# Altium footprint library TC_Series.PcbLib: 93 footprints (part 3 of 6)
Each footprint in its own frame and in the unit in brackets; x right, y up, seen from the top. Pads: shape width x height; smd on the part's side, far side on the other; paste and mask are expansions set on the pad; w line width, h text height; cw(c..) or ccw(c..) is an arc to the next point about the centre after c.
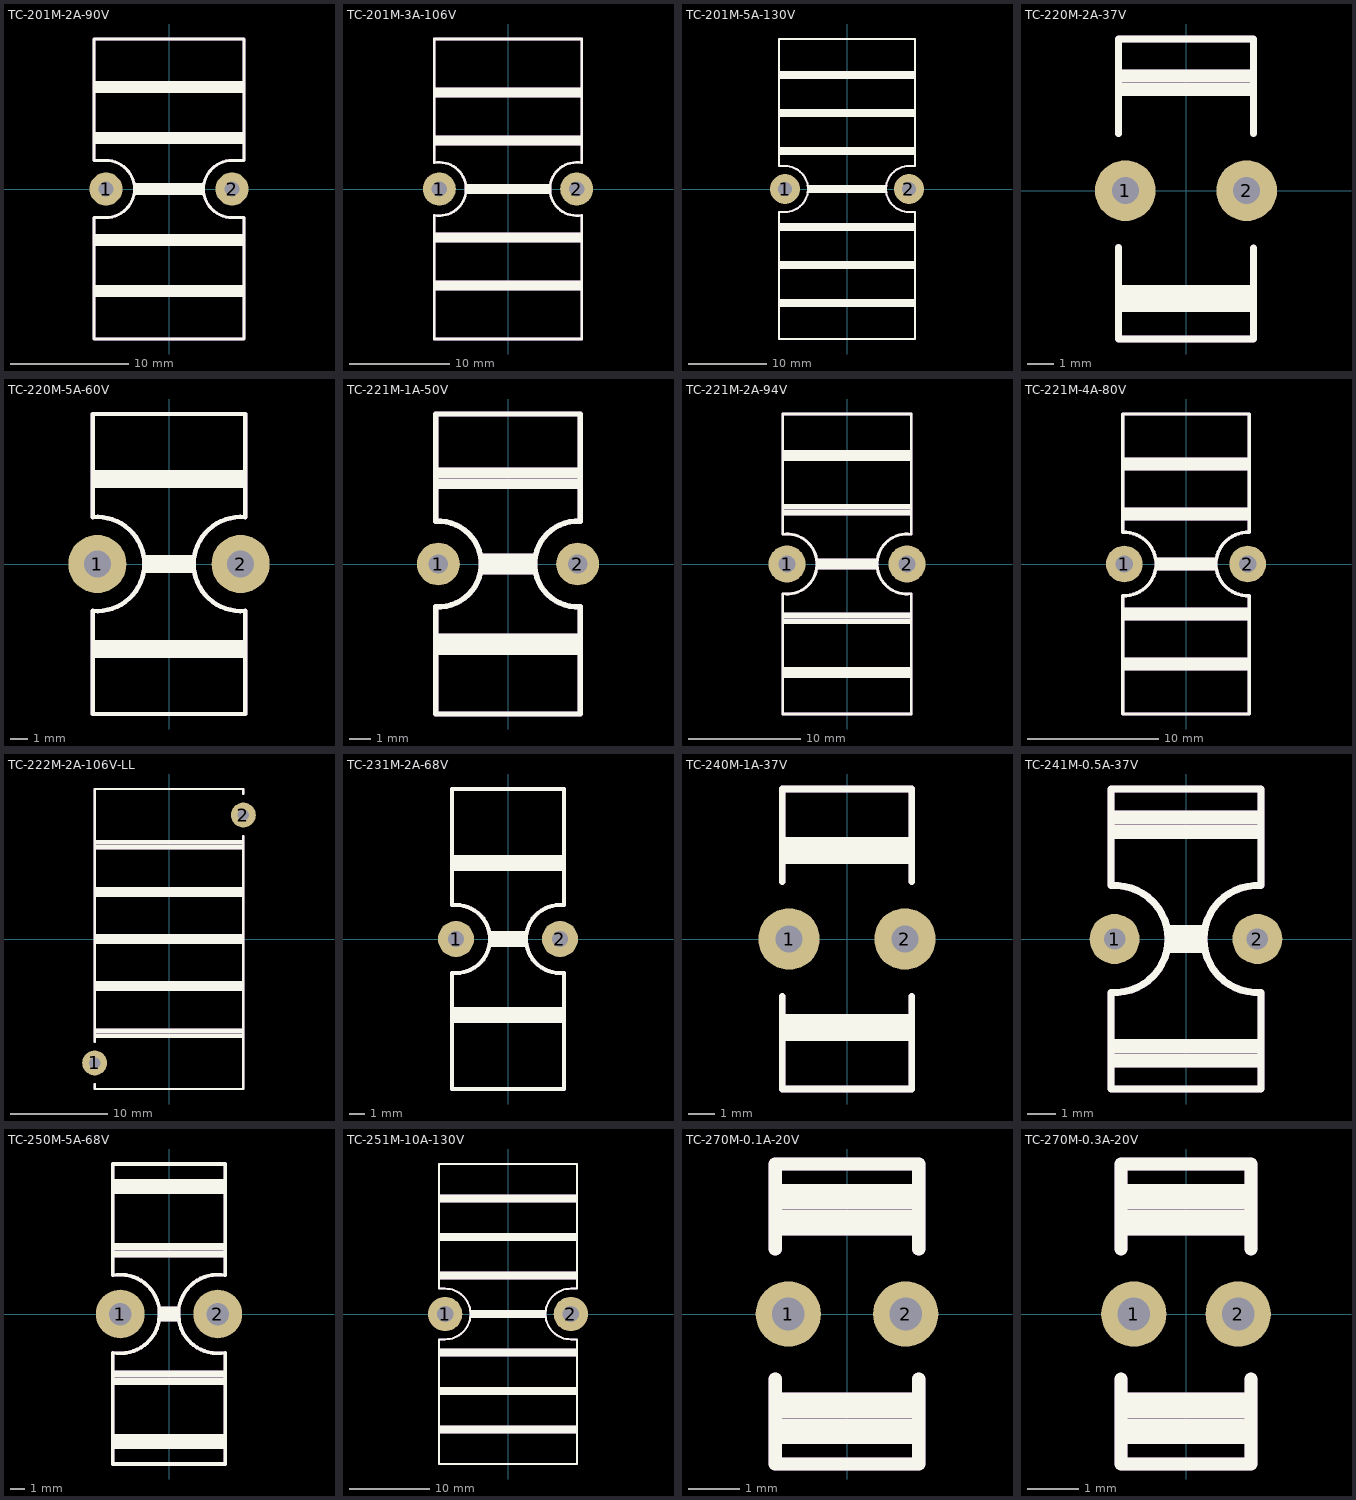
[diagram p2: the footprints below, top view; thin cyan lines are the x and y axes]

## TC-201M-2A-90V [mil]
pads (2):
  round 110 hole 50: 1(-210,0) 2(210,0)
Top Overlay:
  lines w10: -250,-500 -250,-95 -210,-95 ccw(c-210,0) -210,95 -250,95 -250,500 250,500 250,95 210,95 ccw(c210,0) 210,-95 250,-95 250,-500 -250,-500
  lines w19.68: -245,-350 245,-350 ; -245,-330 245,-330 ; -245,-180 245,-180 ; -245,-160 245,-160 ; -245,160 245,160 ; -245,180 245,180 ; -245,330 245,330 ; -245,350 245,350 ; -110,-10 110,-10 ; -110,10 110,10
Mechanical 29:
  lines w10: -250,-500 -250,-95 -210,-95 ccw(c-210,0) -210,95 -250,95 -250,500 250,500 250,95 210,95 ccw(c210,0) 210,-95 250,-95 250,-500 -250,-500
  lines w19.68: -245,-350 245,-350 ; -245,-330 245,-330 ; -245,-180 245,-180 ; -245,-160 245,-160 ; -245,160 245,160 ; -245,180 245,180 ; -245,330 245,330 ; -245,350 245,350 ; -110,-10 110,-10 ; -110,10 110,10
  text "'.Designator'" at -1750,-64.85 h400

## TC-201M-3A-106V [mil]
pads (2):
  round 130 hole 60: 1(-270,0) 2(270,0)
Top Overlay:
  lines w10: -290,-103.15 -290,-590 290,-590 290,-103.53 ; -290,103.53 -290,590 290,590 290,103.53 ; -289.92,103.09 cw(c-270,0) -289.65,-103.15 ; 289.92,-103.09 cw(c270,0) 289.92,103.09
  lines w19.68: -285,-390 285,-390 ; -285,-370 285,-370 ; -285,-200 285,-200 ; -285,-180 285,-180 ; -285,180 285,180 ; -285,200 285,200 ; -285,370 285,370 ; -285,390 285,390 ; -160,-10 160,-10 ; -160,10 160,10
Mechanical 29:
  lines w10: -290,-103.15 -290,-590 290,-590 290,-103.53 ; -290,103.53 -290,590 290,590 290,103.53 ; -289.92,103.09 cw(c-270,0) -289.65,-103.15 ; 289.92,-103.09 cw(c270,0) 289.92,103.09
  lines w19.68: -285,-390 285,-390 ; -285,-370 285,-370 ; -285,-200 285,-200 ; -285,-180 285,-180 ; -285,180 285,180 ; -285,200 285,200 ; -285,370 285,370 ; -285,390 285,390 ; -160,-10 160,-10 ; -160,10 160,10
  text "'.Designator'" at -1750,-64.85 h400

## TC-201M-5A-130V [mil]
pads (2):
  round 150 hole 70: 1(-310,0) 2(310,0)
Top Overlay:
  lines w10: -340,-750 -340,-115 -310,-115 ccw(c-310,0) -310,115 -340,115 -340,750 340,750 340,115 310,115 ccw(c310,0) 310,-115 340,-115 340,-750 -340,-750
  lines w19.68: -335,-580 335,-580 ; -335,-560 335,-560 ; -335,-390 335,-390 ; -335,-370 335,-370 ; -335,-200 335,-200 ; -335,-180 335,-180 ; -335,180 335,180 ; -335,200 335,200 ; -335,370 335,370 ; -335,390 335,390 ; -335,560 335,560 ; -335,580 335,580 ; -190,-10 190,-10 ; -190,10 190,10
Mechanical 29:
  lines w10: -340,-750 -340,-115 -310,-115 ccw(c-310,0) -310,115 -340,115 -340,750 340,750 340,115 310,115 ccw(c310,0) 310,-115 340,-115 340,-750 -340,-750
  lines w19.68: -335,-580 335,-580 ; -335,-560 335,-560 ; -335,-390 335,-390 ; -335,-370 335,-370 ; -335,-200 335,-200 ; -335,-180 335,-180 ; -335,180 335,180 ; -335,200 335,200 ; -335,370 335,370 ; -335,390 335,390 ; -335,560 335,560 ; -335,580 335,580 ; -190,-10 190,-10 ; -190,10 190,10
  text "'.Designator'" at -1750,-64.85 h400

## TC-220M-2A-37V [mil]
pads (2):
  round 90 hole 40: 1(-90,0) 2(90,0)
Top Overlay:
  lines w10: -100,-84.42 -100,-220 100,-220 100,-85 ; -100,84.42 -100,225 100,225 100,85
  lines w19.68: -95,-170 95,-170 ; -95,-150 95,-150 ; -95,150 95,150 ; -95,170 95,170
Mechanical 29:
  lines w10: -100,-84.42 -100,-220 100,-220 100,-85 ; -100,84.42 -100,225 100,225 100,85
  lines w19.68: -95,-170 95,-170 ; -95,-150 95,-150 ; -95,150 95,150 ; -95,170 95,170
  text "'.Designator'" at -750,-37.45 h200

## TC-220M-5A-60V [mil]
pads (2):
  round 130 hole 60: 1(-160,0) 2(160,0)
Top Overlay:
  lines w10: -170,-105 -170,-335 170,-335 170,-105 ; -170,105 -170,335 170,335 170,105 ; -169.96,-104.53 ccw(c-160,0) -169.95,104.53 ; 169.96,-104.53 cw(c160,0) 169.95,104.53
  lines w19.68: -165,-200 165,-200 ; -165,-180 165,-180 ; -165,180 165,180 ; -165,200 165,200 ; -50,-10 50,-10 ; -50,10 50,10
Mechanical 29:
  lines w10: -170,-105 -170,-335 170,-335 170,-105 ; -170,105 -170,335 170,335 170,105 ; -169.96,-104.53 ccw(c-160,0) -169.95,104.53 ; 169.96,-104.53 cw(c160,0) 169.95,104.53
  lines w19.68: -165,-200 165,-200 ; -165,-180 165,-180 ; -165,180 165,180 ; -165,200 165,200 ; -50,-10 50,-10 ; -50,10 50,10
  text "'.Designator'" at -1750,-64.85 h400

## TC-221M-1A-50V [mil]
pads (2):
  round 80 hole 36: 1(-130,0) 2(130,0)
Top Overlay:
  lines w10: -135,-79.86 -135,-280 135,-280 135,-79.86 ; -135,79.86 -135,279.87 ; -135,280 135,280 ; -134.7,-79.86 ccw(c-130,0) -134.7,79.86 ; 134.7,-79.86 cw(c130,0) 134.71,79.86 ; 135,79.86 135,279.87
  lines w19.68: -130,-160 130,-160 ; -130,-140 130,-140 ; -130,150 130,150 ; -130,170 130,170 ; -45,-10 45,-10 ; -45,10 45,10
Mechanical 29:
  lines w10: -135,-79.86 -135,-280 135,-280 135,-79.86 ; -135,79.86 -135,279.87 ; -135,280 135,280 ; -134.7,-79.86 ccw(c-130,0) -134.7,79.86 ; 134.7,-79.86 cw(c130,0) 134.71,79.86 ; 135,79.86 135,279.87
  lines w19.68: -130,-160 130,-160 ; -130,-140 130,-140 ; -130,150 130,150 ; -130,170 130,170 ; -45,-10 45,-10 ; -45,10 45,10
  text "'.Designator'" at -1750,-64.85 h400

## TC-221M-2A-94V [mil]
pads (2):
  round 130 hole 60: 1(-210,0) 2(210,0)
Top Overlay:
  lines w10: -225,-103.94 -225,-525 225,-525 225,-103.94 ; -225,103.94 -225,525 225,525 225,103.94 ; -224.85,-103.94 ccw(c-210,0) -224.85,103.94 ; 224.85,-103.94 cw(c210,0) 224.85,103.94
  lines w19.68: -220,-390 220,-390 ; -220,-370 220,-370 ; -220,-200 220,-200 ; -220,-180 220,-180 ; -220,180 220,180 ; -220,200 220,200 ; -220,370 220,370 ; -220,390 220,390 ; -100,-10 100,-10 ; -100,10 100,10
Mechanical 29:
  lines w10: -225,-103.94 -225,-525 225,-525 225,-103.94 ; -225,103.94 -225,525 225,525 225,103.94 ; -224.85,-103.94 ccw(c-210,0) -224.85,103.94 ; 224.85,-103.94 cw(c210,0) 224.85,103.94
  lines w19.68: -220,-390 220,-390 ; -220,-370 220,-370 ; -220,-200 220,-200 ; -220,-180 220,-180 ; -220,180 220,180 ; -220,200 220,200 ; -220,370 220,370 ; -220,390 220,390 ; -100,-10 100,-10 ; -100,10 100,10
  text "'.Designator'" at -1750,-64.85 h400

## TC-221M-4A-80V [mil]
pads (2):
  round 110 hole 52: 1(-185,0) 2(185,0)
Top Overlay:
  lines w10: 190,-95 190,-450 -190,-450 -190,-94.87 ccw(c-185,0) -189.99,94.87 -190,450 190,450 190,95 ; 189.99,-94.87 cw(c185,0) 189.99,94.87
  lines w19.68: -185,-310 185,-310 ; -185,-290 185,-290 ; -185,-160 185,-160 ; -185,-140 185,-140 ; -185,140 185,140 ; -185,160 185,160 ; -185,290 185,290 ; -185,310 185,310 ; -85,-10 85,-10 ; -85,10 85,10
Mechanical 29:
  lines w10: 190,-95 190,-450 -190,-450 -190,-94.87 ccw(c-185,0) -189.99,94.87 -190,450 190,450 190,95 ; 189.99,-94.87 cw(c185,0) 189.99,94.87
  lines w19.68: -185,-310 185,-310 ; -185,-290 185,-290 ; -185,-160 185,-160 ; -185,-140 185,-140 ; -185,140 185,140 ; -185,160 185,160 ; -185,290 185,290 ; -185,310 185,310 ; -85,-10 85,-10 ; -85,10 85,10
  text "'.Designator'" at -1750,-64.85 h400

## TC-222M-2A-106V-LL [mil]
pads (2):
  round 100 hole 46: 1(-300,-500) 2(300,500)
Top Overlay:
  lines w10: -300,-585 -300,-605 300,-605 300,415 ; -300,-415 -300,605 300,605 300,585
  lines w19.68: -295,-390 295,-390 ; -295,-370 295,-370 ; -295,-200 295,-200 ; -295,-180 295,-180 ; -295,-10 295,-10 ; -295,10 295,10 ; -295,180 295,180 ; -295,200 295,200 ; -295,370 295,370 ; -295,390 295,390
Mechanical 29:
  lines w10: -300,-585 -300,-605 300,-605 300,415 ; -300,-415 -300,605 300,605 300,585
  lines w19.68: -295,-390 295,-390 ; -295,-370 295,-370 ; -295,-200 295,-200 ; -295,-180 295,-180 ; -295,-10 295,-10 ; -295,10 295,10 ; -295,180 295,180 ; -295,200 295,200 ; -295,370 295,370 ; -295,390 295,390
  text "'.Designator'" at -1750,-64.85 h400

## TC-231M-2A-68V [mil]
pads (2):
  round 90 hole 40: 1(-130,0) 2(130,0)
Top Overlay:
  lines w10: -140,84.42 -140,375 140,375 140,84.83 ; -139.93,84.42 cw(c-130,0) -140,-84.41 -140,-375 140,-375 140,-84.83 ; 139.95,-84.42 cw(c130,0) 139.95,84.42
  lines w19.68: -135,-200 135,-200 ; -135,-180 135,-180 ; -135,180 135,180 ; -135,200 135,200 ; -40,-10 40,-10 ; -40,10 40,10
Mechanical 29:
  lines w10: -140,84.42 -140,375 140,375 140,84.83 ; -139.93,84.42 cw(c-130,0) -140,-84.41 -140,-375 140,-375 140,-84.83 ; 139.95,-84.42 cw(c130,0) 139.95,84.42
  lines w19.68: -135,-200 135,-200 ; -135,-180 135,-180 ; -135,180 135,180 ; -135,200 135,200 ; -40,-10 40,-10 ; -40,10 40,10
  text "'.Designator'" at -1750,-64.85 h400

## TC-240M-1A-37V [mil]
pads (2):
  round 90 hole 40: 1(-85,0) 2(85,0)
Top Overlay:
  lines w10: -95,-84.34 -95,-220 95,-220 95,-84.34 ; -95,84.25 -95,220 95,220 95,84.25
  lines w19.68: -90,-140 90,-140 ; -90,-120 90,-120 ; -90,120 90,120 ; -90,140 90,140
Mechanical 29:
  lines w10: -95,-84.34 -95,-220 95,-220 95,-84.34 ; -95,84.25 -95,220 95,220 95,84.25
  lines w19.68: -90,-140 90,-140 ; -90,-120 90,-120 ; -90,120 90,120 ; -90,140 90,140
  text "'.Designator'" at -700,-37.45 h200

## TC-241M-0.5A-37V [mil]
pads (2):
  round 70 hole 30: 1(-100,0) 2(100,0)
Top Overlay:
  lines w10: -105,-74.83 ccw(c-100,0) -105,74.83 ; -105,-74.78 -105,-210 105,-210 105,-74.78 ; -105,74.78 -105,210 105,210 105,74.78 ; 105,-74.83 cw(c100,0) 105,74.83
  lines w19.68: -100,-170 100,-170 ; -100,-150 100,-150 ; -100,150 100,150 ; -100,170 100,170 ; -20,-10 20,-10 ; -20,10 20,10
Mechanical 29:
  lines w10: -105,-74.83 ccw(c-100,0) -105,74.83 ; -105,-74.78 -105,-210 105,-210 105,-74.78 ; -105,74.78 -105,210 105,210 105,74.78 ; 105,-74.83 cw(c100,0) 105,74.83
  lines w19.68: -100,-170 100,-170 ; -100,-150 100,-150 ; -100,150 100,150 ; -100,170 100,170 ; -20,-10 20,-10 ; -20,10 20,10
  text "'.Designator'" at -1750,-64.85 h400

## TC-250M-5A-68V [mil]
pads (2):
  round 130 hole 60: 1(-130,0) 2(130,0)
Top Overlay:
  lines w10: -150,-103.15 -150,-400 150,-400 150,-103.15 ; -149.99,-103.08 ccw(c-130,0) -149.65,103.15 ; -150,103.15 -150,400 150,400 150,103.15 ; 149.65,103.15 ccw(c130,0) 149.99,-103.08
  lines w19.68: -145,-350 145,-350 ; -145,-330 145,-330 ; -145,-180 145,-180 ; -145,-160 145,-160 ; -145,160 145,160 ; -145,180 145,180 ; -145,330 145,330 ; -145,350 145,350 ; -20,-10 20,-10 ; -20,10 20,10
Mechanical 29:
  lines w10: -150,-103.15 -150,-400 150,-400 150,-103.15 ; -149.99,-103.08 ccw(c-130,0) -149.65,103.15 ; -150,103.15 -150,400 150,400 150,103.15 ; 149.65,103.15 ccw(c130,0) 149.99,-103.08
  lines w19.68: -145,-350 145,-350 ; -145,-330 145,-330 ; -145,-180 145,-180 ; -145,-160 145,-160 ; -145,160 145,160 ; -145,180 145,180 ; -145,330 145,330 ; -145,350 145,350 ; -20,-10 20,-10 ; -20,10 20,10
  text "'.Designator'" at -1750,-64.85 h400

## TC-251M-10A-130V [mil]
pads (2):
  round 170 hole 80: 1(-310,0) 2(310,0)
Top Overlay:
  lines w10: -340,-740 -340,-125 -310,-125 ccw(c-310,0) -310,125 -340,125 -340,740 340,740 340,125 310,125 ccw(c310,0) 310,-125 340,-125 340,-740 -340,-740
  lines w19.68: -335,-580 335,-580 ; -335,-560 335,-560 ; -335,-390 335,-390 ; -335,-370 335,-370 ; -335,-200 335,-200 ; -335,-180 335,-180 ; -335,180 335,180 ; -335,200 335,200 ; -335,370 335,370 ; -335,390 335,390 ; -335,560 335,560 ; -335,580 335,580 ; -180,-10 180,-10 ; -180,10 180,10
Mechanical 29:
  lines w10: -340,-740 -340,-125 -310,-125 ccw(c-310,0) -310,125 -340,125 -340,740 340,740 340,125 310,125 ccw(c310,0) 310,-125 340,-125 340,-740 -340,-740
  lines w19.68: -335,-580 335,-580 ; -335,-560 335,-560 ; -335,-390 335,-390 ; -335,-370 335,-370 ; -335,-200 335,-200 ; -335,-180 335,-180 ; -335,180 335,180 ; -335,200 335,200 ; -335,370 335,370 ; -335,390 335,390 ; -335,560 335,560 ; -335,580 335,580 ; -180,-10 180,-10 ; -180,10 180,10
  text "'.Designator'" at -1750,-64.85 h400

## TC-270M-0.1A-20V [mil]
pads (2):
  round 50 hole 25: 1(-45,0) 2(45,0)
Top Overlay:
  lines w10: -55,-50 -55,-115 55,-115 55,-50 ; -55,50 -55,115 55,115 55,50
  lines w19.68: -50,-90 50,-90 ; -50,-70 50,-70 ; -50,70 50,70 ; -50,90 50,90
Mechanical 29:
  lines w10: -55,-50 -55,-115 55,-115 55,-50 ; -55,50 -55,115 55,115 55,50
  lines w19.68: -50,-90 50,-90 ; -50,-70 50,-70 ; -50,70 50,70 ; -50,90 50,90
  text "'.Designator'" at -825,-37.45 h200

## TC-270M-0.3A-20V [mil]
pads (2):
  round 50 hole 25: 1(-40,0) 2(40,0)
Top Overlay:
  lines w10: -50,-50 -50,-115 50,-115 50,-50 ; -50,50 -50,115 50,115 50,50
  lines w19.68: -45,-90 45,-90 ; -45,-70 45,-70 ; -45,70 45,70 ; -45,90 45,90
Mechanical 29:
  lines w10: -50,-50 -50,-115 50,-115 50,-50 ; -50,50 -50,115 50,115 50,50
  lines w19.68: -45,-90 45,-90 ; -45,-70 45,-70 ; -45,70 45,70 ; -45,90 45,90
  text "'.Designator'" at -875,-12.45 h200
